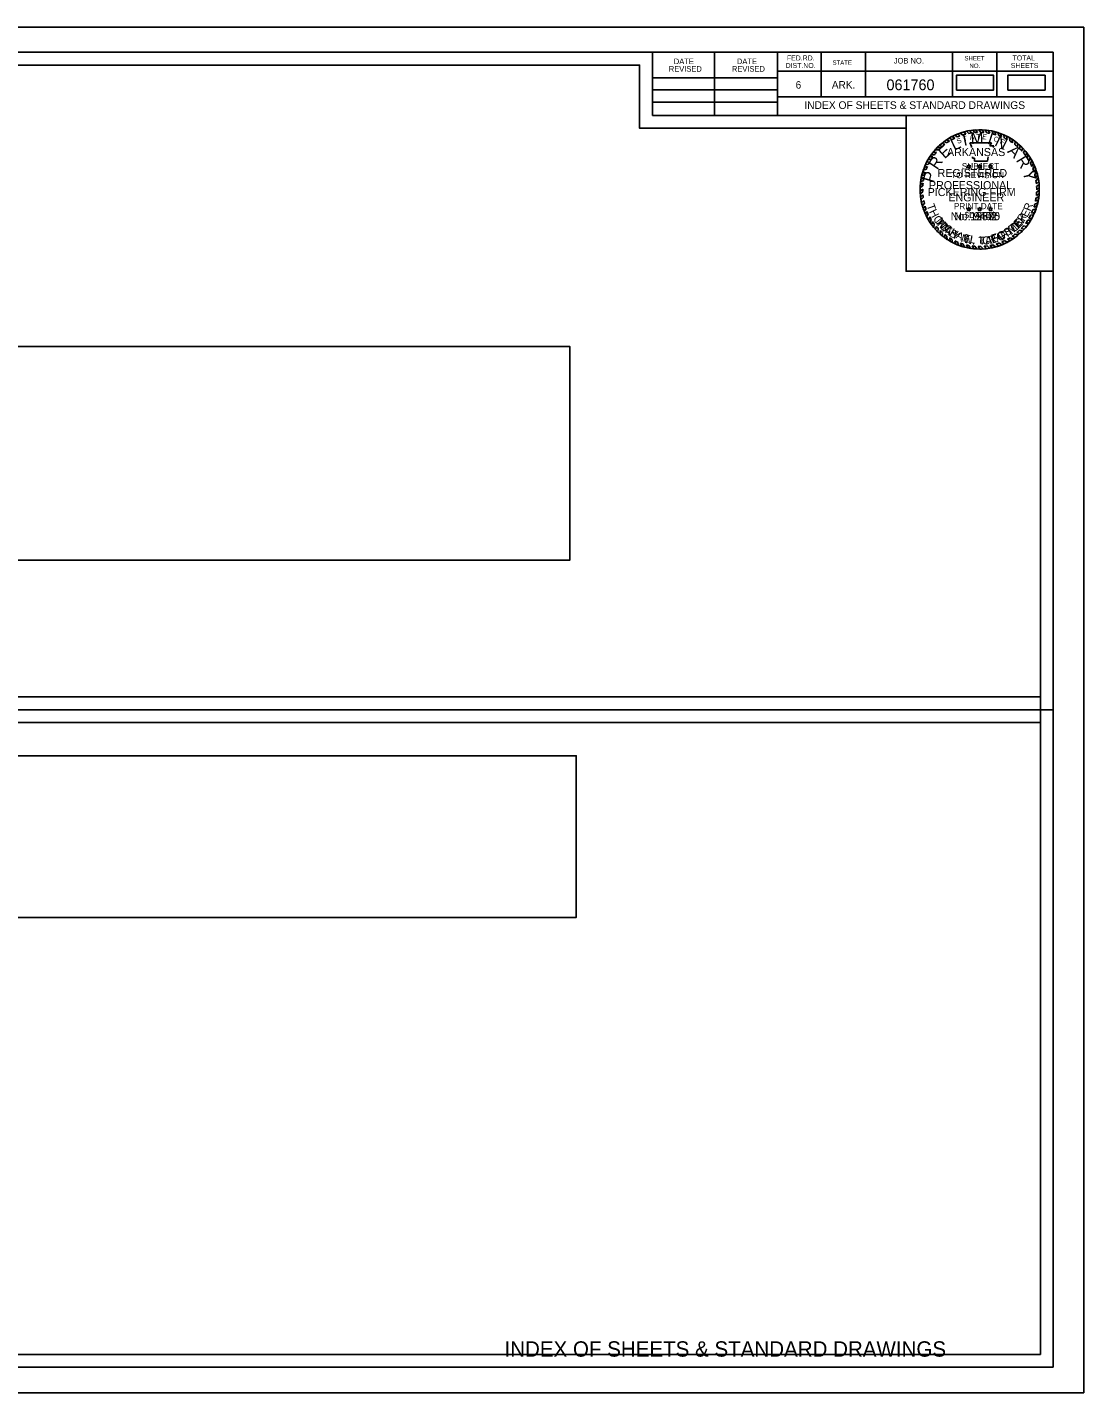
# Model space of a CAD drawing. Extents: x -12 to 321, y -380127 to -379914.
# Drawn here: x 155.9 to 320.9, y -380127 to -379913.7 of the extents above; entities that cross this region are included whole.
import ezdxf

# ---------------------------------------------------------------- set-up
doc = ezdxf.new("R2010")
doc.units = 0
for name, color, linetype in [('Default', 7, 'Continuous'), ('R_Border', 7, 'Continuous'), ('R_Border Notes', 7, 'Continuous'), ('R_Border Plan-Plan', 7, 'Continuous'), ('R_Border Title', 7, 'Continuous'), ('R_No Plot', 7, 'Continuous'), ('STAMP_PE_CRAFTON', 7, 'Continuous'), ('STAMP_PE_FOSTER', 7, 'Continuous'), ('STAMP_PE_SEAL-INFO', 7, 'Continuous'), ('STAMP_PE_TAEGTMEYER', 7, 'Continuous'), ('STAMP_PE_TXT', 7, 'Continuous'), ('STAMP_PRELIMINARY', 7, 'Continuous')]:
    doc.layers.add(name, color=color, linetype=linetype)

msp = doc.modelspace()

# ---------------------------------------------------------------- linework, layer by layer
at = {"layer": 'Default'}
for points in [[(301.03, -379923.52), (306.86, -379923.52), (306.86, -379921.21), (301.03, -379921.21)], [(309.07, -379923.52), (314.9, -379923.52), (314.9, -379921.21), (309.07, -379921.21)], [(84.69, -379996.99), (240.61, -379996.99), (240.61, -379963.58), (84.69, -379963.58)], [(83.66, -380052.8), (241.64, -380052.8), (241.64, -380027.52), (83.66, -380027.52)]]:
    msp.add_lwpolyline(points, close=True, dxfattribs=at)
at = {"layer": 'R_Border'}
for p, q in [((0, -379917.61), (316.18, -379917.61)), ((253.54, -379927.49), (253.54, -379917.61)), ((263.22, -379927.49), (263.22, -379917.61)), ((273.08, -379917.61), (273.08, -379927.49)), ((279.92, -379917.61), (279.92, -379924.55)), ((286.86, -379917.61), (286.86, -379924.55)), ((300.44, -379917.61), (300.44, -379924.55)), ((307.38, -379917.61), (307.38, -379924.55)), ((316.18, -380123.07), (316.18, -379917.61)), ((253.54, -379921.63), (273.08, -379921.63)), ((316.18, -379920.55), (273.08, -379920.55)), ((316.18, -379920.53), (316.18, -379920.53)), ((253.54, -379923.49), (273.08, -379923.49)), ((253.54, -379925.43), (273.08, -379925.43)), ((316.18, -379924.55), (273.08, -379924.55)), ((276.04, -379924.55), (316.18, -379924.55)), ((316.18, -379927.49), (253.54, -379927.49)), ((316.18, -380123.07), (0, -380123.07))]:
    msp.add_line(p, q, dxfattribs=at)
at = {"layer": 'R_Border Plan-Plan'}
msp.add_line((0, -380020.34), (316.18, -380020.34), dxfattribs=at)
at = {"layer": 'R_No Plot'}
for points in [[(-12.41, -379913.71), (320.93, -379913.71), (320.93, -380127.05), (-12.41, -380127.05)], [(314.18, -380018.34), (2, -380018.34), (2, -379919.61), (251.54, -379919.61), (251.54, -379929.49), (269.08, -379929.49), (293.18, -379929.49), (293.18, -379951.82), (314.18, -379951.82)], [(2, -379919.61), (251.54, -379919.61), (251.54, -379929.49), (269.08, -379929.49), (293.18, -379929.49), (293.18, -379951.82), (314.18, -379951.82), (314.18, -380121.07), (2, -380121.07)], [(293.18, -379927.49), (316.18, -379927.49), (316.18, -379951.82), (293.18, -379951.82)], [(2, -380022.34), (314.18, -380022.34), (314.18, -380121.07), (2, -380121.07)]]:
    msp.add_lwpolyline(points, close=True, dxfattribs=at)
at = {"layer": 'STAMP_PE_SEAL-INFO'}
for p, q in [((300.35, -379930.79), (300.82, -379931.01)), ((300.78, -379930.57), (301.17, -379930.85)), ((301.29, -379930.36), (301.59, -379930.68)), ((301.64, -379930.23), (302.02, -379930.54)), ((302.23, -379930.05), (302.52, -379930.4)), ((302.62, -379929.95), (302.97, -379930.29)), ((303.1, -379929.86), (303.4, -379930.22)), ((303.62, -379929.78), (303.9, -379930.16)), ((304.35, -379930.14), (304.04, -379929.74)), ((304.85, -379930.13), (304.57, -379929.72)), ((305.31, -379930.15), (305.05, -379929.73)), ((305.81, -379930.2), (305.52, -379929.76)), ((306.24, -379930.27), (305.98, -379929.81)), ((306.8, -379930.39), (306.63, -379929.93)), ((307.2, -379930.49), (307.04, -379930.03)), ((307.65, -379930.64), (307.51, -379930.16)), ((308.07, -379930.8), (307.93, -379930.31)), ((308.53, -379931.01), (308.43, -379930.51)), ((308.98, -379931.24), (308.89, -379930.73)), ((297.72, -379932.84), (298.24, -379932.88)), ((298.04, -379932.5), (298.59, -379932.54)), ((298.38, -379932.17), (298.84, -379932.31)), ((298.72, -379931.87), (299.25, -379931.97)), ((299.1, -379931.55), (299.55, -379931.75)), ((299.52, -379931.28), (299.96, -379931.48)), ((299.9, -379931.04), (300.34, -379931.26)), ((303.15, -379931.75), (306.5, -379931.75)), ((303.27, -379932.06), (303.15, -379931.75)), ((303.38, -379932.36), (303.27, -379932.06)), ((303.39, -379932.47), (303.38, -379932.36)), ((306.5, -379931.75), (306.27, -379932.24)), ((306.27, -379932.24), (306.9, -379932.24)), ((306.9, -379932.24), (306.76, -379932.47)), ((309.37, -379931.46), (309.33, -379930.96)), ((309.8, -379931.75), (309.77, -379931.23)), ((310.16, -379932.02), (310.2, -379931.53)), ((310.61, -379932.39), (310.63, -379931.87)), ((310.92, -379932.68), (310.99, -379932.18)), ((311.28, -379933.05), (311.35, -379932.53)), ((311.55, -379933.37), (311.69, -379932.9)), ((296.38, -379934.79), (296.88, -379934.73)), ((296.61, -379934.37), (297.1, -379934.35)), ((296.86, -379933.97), (297.38, -379933.93)), ((297.1, -379933.62), (297.6, -379933.63)), ((297.37, -379933.25), (297.92, -379933.23)), ((303.58, -379934.18), (303.55, -379933.96)), ((303.89, -379934.18), (303.58, -379934.18)), ((303.89, -379934.61), (303.89, -379934.18)), ((305.92, -379934.61), (303.89, -379934.61)), ((305.94, -379934.27), (305.92, -379934.61)), ((306.01, -379933.96), (305.94, -379934.27)), ((311.88, -379933.79), (312.01, -379933.29)), ((312.1, -379934.1), (312.28, -379933.64)), ((312.41, -379934.6), (312.59, -379934.11)), ((312.61, -379934.97), (312.83, -379934.52)), ((312.84, -379935.45), (313.06, -379934.97)), ((295.96, -379937.18), (295.5, -379937.42)), ((295.6, -379936.93), (296.07, -379936.74)), ((295.7, -379936.52), (296.18, -379936.35)), ((295.86, -379936.02), (296.35, -379935.88)), ((296.01, -379935.61), (296.52, -379935.47)), ((296.2, -379935.18), (296.7, -379935.08)), ((312.98, -379935.79), (313.24, -379935.35)), ((313.17, -379936.34), (313.44, -379935.86)), ((313.28, -379936.7), (313.57, -379936.25)), ((313.41, -379937.26), (313.73, -379936.81)), ((295.78, -379938.5), (295.36, -379938.75)), ((295.77, -379938.99), (295.36, -379939.32)), ((295.82, -379938.07), (295.38, -379938.35)), ((295.88, -379937.63), (295.43, -379937.86)), ((313.48, -379937.64), (313.84, -379937.29)), ((313.55, -379938.15), (313.92, -379937.81)), ((313.58, -379938.57), (313.97, -379938.28)), ((313.58, -379939.49), (314, -379939.21)), ((313.59, -379939.09), (314, -379938.76)), ((295.77, -379939.4), (295.38, -379939.72)), ((295.81, -379939.89), (295.44, -379940.25)), ((295.86, -379940.32), (295.5, -379940.69)), ((295.94, -379940.78), (295.6, -379941.15)), ((296.03, -379941.2), (295.72, -379941.61)), ((313.29, -379941.34), (313.77, -379941.14)), ((313.4, -379940.88), (313.86, -379940.69)), ((313.49, -379940.39), (313.93, -379940.17)), ((313.54, -379940), (313.98, -379939.74)), ((296.15, -379941.64), (295.86, -379942.06)), ((296.3, -379942.07), (296.01, -379942.48)), ((296.46, -379942.49), (296.2, -379942.92)), ((296.63, -379942.88), (296.41, -379943.34)), ((296.87, -379943.34), (296.68, -379943.83)), ((312.36, -379943.56), (312.87, -379943.51)), ((312.64, -379943.06), (313.12, -379942.99)), ((312.8, -379942.73), (313.29, -379942.63)), ((313.01, -379942.21), (313.49, -379942.08)), ((313.15, -379941.83), (313.64, -379941.63)), ((297.1, -379943.74), (296.92, -379944.21)), ((297.31, -379944.05), (297.2, -379944.6)), ((297.59, -379944.44), (297.49, -379944.97)), ((297.89, -379944.82), (297.8, -379945.34)), ((298.19, -379945.16), (298.13, -379945.68)), ((298.52, -379945.48), (298.49, -379946.01)), ((310.91, -379945.42), (311.35, -379945.56)), ((311.16, -379945.16), (311.64, -379945.25)), ((311.55, -379944.73), (312.01, -379944.81)), ((311.85, -379944.33), (312.36, -379944.33)), ((312.19, -379943.84), (312.67, -379943.85)), ((298.86, -379945.8), (298.86, -379946.32)), ((299.22, -379946.09), (299.24, -379946.61)), ((299.56, -379946.34), (299.6, -379946.86)), ((299.99, -379946.62), (300.05, -379947.13)), ((300.34, -379946.83), (300.43, -379947.34)), ((300.82, -379947.08), (300.97, -379947.6)), ((301.19, -379947.25), (301.36, -379947.76)), ((301.68, -379947.44), (301.89, -379947.94)), ((302.09, -379947.57), (302.32, -379948.06)), ((302.6, -379947.71), (302.81, -379948.18)), ((303, -379947.8), (303.24, -379948.25)), ((306.28, -379947.81), (306.67, -379948.15)), ((306.77, -379947.71), (307.15, -379948.03)), ((307.23, -379947.58), (307.65, -379947.88)), ((307.73, -379947.42), (308.17, -379947.69)), ((308.14, -379947.26), (308.57, -379947.52)), ((308.6, -379947.05), (309.09, -379947.26)), ((309.01, -379946.83), (309.43, -379947.07)), ((309.43, -379946.59), (309.88, -379946.78)), ((309.77, -379946.36), (310.21, -379946.55)), ((310.23, -379946.02), (310.7, -379946.16)), ((310.5, -379945.79), (310.97, -379945.92)), ((303.5, -379947.88), (303.74, -379948.32)), ((303.93, -379947.93), (304.21, -379948.35)), ((304.42, -379947.95), (304.72, -379948.37)), ((304.88, -379947.95), (305.22, -379948.35)), ((305.4, -379947.93), (305.72, -379948.31)), ((305.84, -379947.88), (306.21, -379948.24))]:
    msp.add_line(p, q, dxfattribs=at)
for radius, start, end in [(9.32, 117.6544, 120.8099), (9.32, 111.3124, 114.7026), (8.91, 110.3086, 113.1659), (9.32, 105.2339, 109.0352), (8.91, 104.0352, 107.3615), (9.32, 99.7525, 102.7765), (8.91, 98.258, 101.0329), (9.32, 93.9381, 96.5517), (8.91, 92.1102, 95.0367), (9.32, 87.7298, 90.6707), (8.91, 85.9628, 88.9097), (9.32, 81.9732, 84.8236), (8.91, 79.9264, 82.696), (9.32, 75.3125, 77.9426), (8.91, 73.5575, 76.2314), (9.32, 69.6061, 72.3058), (8.91, 67.6248, 70.504), (9.32, 63.1329, 66.2704), (9.32, 135.4021, 138.3031), (8.91, 133.1331, 136.2562), (9.32, 129.7326, 132.5376), (8.91, 127.5297, 130.9683), (9.32, 123.6199, 126.5906), (8.91, 121.9746, 125.11), (8.91, 115.6869, 119.1583), (8.91, 61.1558, 64.3784), (9.32, 56.9003, 60.0942), (8.91, 54.9238, 58.2702), (8.91, 48.3016, 52.0395), (9.32, 50.3492, 53.7159), (8.91, 42.2212, 45.5512), (9.32, 44.3405, 47.3929), (9.32, 38.1247, 41.2316), (9.32, 152.864, 155.5189), (9.32, 147.0072, 149.899), (8.91, 151.0315, 153.573), (9.32, 141.6056, 144.4486), (8.91, 145.0197, 148.2104), (8.91, 139.301, 142.5873), (8.91, 36.135, 39.5311), (8.91, 29.9032, 33.6645), (9.32, 31.9614, 35.4294), (8.91, 23.7732, 27.2211), (9.32, 25.9391, 29.0125), (9.32, 164.3068, 166.894), (9.32, 158.4077, 161.0701), (8.91, 167.9048, 170.9039), (8.91, 162.4331, 165.0013), (8.91, 156.3402, 159.2319), (8.91, 17.6802, 21.4251), (9.32, 19.9538, 23.3141), (8.91, 11.5444, 15.2364), (9.32, 13.8421, 17.4447), (9.32, 175.7409, 178.2066), (9.32, 181.7251, 184.1626), (9.32, 170.0003, 172.6878), (8.91, 179.6454, 182.2633), (8.91, 173.73, 176.4734), (8.91, 5.7599, 9.0606), (8.91, 359.7329, 3.0639), (9.32, 7.5852, 10.8621), (9.32, 1.7215, 4.7268), (9.32, 355.7156, 358.9569), (9.32, 187.4204, 190.1927), (9.32, 193.0369, 195.9973), (8.91, 185.4539, 188.234), (8.91, 191.2274, 193.9858), (8.91, 341.777, 345.0925), (8.91, 348.0778, 351.3435), (8.91, 353.8632, 357.1274), (9.32, 343.8925, 347.035), (9.32, 349.8305, 353.0885), (9.32, 198.8967, 201.6281), (8.91, 196.9675, 199.8353), (9.32, 204.5479, 207.4328), (8.91, 202.7761, 205.4791), (8.91, 208.7883, 211.7934), (8.91, 329.5549, 333.2076), (8.91, 335.6038, 339.1858), (9.32, 331.4037, 334.9332), (9.32, 337.3837, 340.9933), (9.32, 210.8636, 213.6571), (9.32, 216.6115, 219.491), (8.91, 214.1838, 217.2747), (9.32, 222.48, 225.3801), (8.91, 220.3909, 223.3056), (8.91, 226.2494, 229.2407), (8.91, 310.7744, 314.3161), (9.32, 312.4518, 315.6633), (8.91, 316.6531, 320.3711), (9.32, 318.2846, 321.8043), (8.91, 323.5851, 327.4407), (9.32, 325.4405, 328.9872), (9.32, 228.3665, 231.348), (8.91, 232.229, 234.9336), (9.32, 234.295, 236.9452), (8.91, 238.2223, 240.8353), (9.32, 240.1977, 242.8613), (8.91, 244.3204, 246.9486), (9.32, 246.576, 249.1558), (8.91, 250.3491, 253.1216), (8.91, 256.505, 259.1192), (8.91, 280.3459, 283.5814), (8.91, 286.6423, 289.9783), (9.32, 288.5709, 291.9733), (8.91, 292.8745, 296.1185), (9.32, 294.6481, 298.2166), (8.91, 299.0768, 302.1724), (9.32, 300.621, 303.8703), (8.91, 304.823, 308.5143), (9.32, 306.3721, 310.208), (9.32, 252.5967, 255.3252), (9.32, 258.4433, 261.1398), (8.91, 262.3783, 265.2012), (9.32, 264.1978, 267.1009), (8.91, 268.3215, 271.277), (9.32, 270.2548, 273.3361), (8.91, 274.6157, 277.4486), (9.32, 276.4239, 279.4357), (9.32, 282.3199, 285.3702)]:
    msp.add_arc((304.68, -379939.04), radius, start, end, dxfattribs=at)
at = {"layer": 'STAMP_PE_TXT'}
for p, q in [((302.86, -379935.47), (302.66, -379935.33)), ((302.66, -379935.33), (302.91, -379935.33)), ((302.78, -379935.71), (302.86, -379935.47)), ((302.98, -379935.56), (302.78, -379935.71)), ((302.91, -379935.33), (302.98, -379935.09)), ((302.98, -379935.09), (303.06, -379935.33)), ((303.18, -379935.71), (302.98, -379935.56)), ((303.06, -379935.33), (303.3, -379935.33)), ((303.3, -379935.33), (303.1, -379935.47)), ((303.1, -379935.47), (303.18, -379935.71)), ((304.56, -379935.47), (304.36, -379935.33)), ((304.36, -379935.33), (304.6, -379935.33)), ((304.48, -379935.71), (304.56, -379935.47)), ((304.68, -379935.56), (304.48, -379935.71)), ((304.6, -379935.33), (304.68, -379935.09)), ((304.68, -379935.09), (304.76, -379935.33)), ((304.88, -379935.71), (304.68, -379935.56)), ((304.76, -379935.33), (305, -379935.33)), ((305, -379935.33), (304.8, -379935.47)), ((304.8, -379935.47), (304.88, -379935.71)), ((306.26, -379935.47), (306.06, -379935.33)), ((306.06, -379935.33), (306.3, -379935.33)), ((306.18, -379935.71), (306.26, -379935.47)), ((306.38, -379935.56), (306.18, -379935.71)), ((306.3, -379935.33), (306.38, -379935.09)), ((306.38, -379935.09), (306.45, -379935.33)), ((306.58, -379935.71), (306.38, -379935.56)), ((306.45, -379935.33), (306.7, -379935.33)), ((306.7, -379935.33), (306.5, -379935.47)), ((306.5, -379935.47), (306.58, -379935.71)), ((302.86, -379942.18), (302.66, -379942.03)), ((302.66, -379942.03), (302.91, -379942.03)), ((302.78, -379942.41), (302.86, -379942.18)), ((302.98, -379942.27), (302.78, -379942.41)), ((302.91, -379942.03), (302.98, -379941.8)), ((302.98, -379941.8), (303.06, -379942.03)), ((303.18, -379942.41), (302.98, -379942.27)), ((303.06, -379942.03), (303.3, -379942.03)), ((303.3, -379942.03), (303.1, -379942.18)), ((303.1, -379942.18), (303.18, -379942.41)), ((304.56, -379942.18), (304.36, -379942.03)), ((304.36, -379942.03), (304.6, -379942.03)), ((304.48, -379942.41), (304.56, -379942.18)), ((304.68, -379942.27), (304.48, -379942.41)), ((304.6, -379942.03), (304.68, -379941.8)), ((304.68, -379941.8), (304.76, -379942.03)), ((304.88, -379942.41), (304.68, -379942.27)), ((304.76, -379942.03), (305, -379942.03)), ((305, -379942.03), (304.8, -379942.18)), ((304.8, -379942.18), (304.88, -379942.41)), ((306.26, -379942.18), (306.06, -379942.03)), ((306.06, -379942.03), (306.3, -379942.03)), ((306.18, -379942.41), (306.26, -379942.18)), ((306.38, -379942.27), (306.18, -379942.41)), ((306.3, -379942.03), (306.38, -379941.8)), ((306.38, -379941.8), (306.45, -379942.03)), ((306.58, -379942.41), (306.38, -379942.27)), ((306.45, -379942.03), (306.7, -379942.03)), ((306.7, -379942.03), (306.5, -379942.18)), ((306.5, -379942.18), (306.58, -379942.41))]:
    msp.add_line(p, q, dxfattribs=at)
at = {"layer": 'STAMP_PRELIMINARY'}
msp.add_circle((304.68, -379939.04), 9.32, dxfattribs=at)

# ---------------------------------------------------------------- texts
at = {"layer": 'R_Border'}
for s, height, p in [('REVISED', 0.879, (256.1, -379920.65)), ('DATE', 0.879, (256.88, -379919.47)), ('REVISED', 0.879, (265.96, -379920.65)), ('DATE', 0.879, (266.74, -379919.47)), ('DIST.NO.', 0.782, (274.36, -379920.07)), ('FED.RD.', 0.782, (274.56, -379918.89)), ('STATE', 0.684, (281.68, -379919.57)), ('JOB NO.', 0.879, (291.26, -379919.37)), ('SHEET', 0.684, (302.3, -379918.89)), ('NO.', 0.684, (303.08, -379920.07)), ('SHEETS', 0.782, (309.54, -379920.07)), ('TOTAL', 0.782, (309.82, -379918.89)), ('6', 1.17, (275.92, -379923.29)), ('ARK.', 1.172, (281.58, -379923.29))]:
    msp.add_text(s, height=height, dxfattribs=at).set_placement(p)
at = {"layer": 'R_Border Notes'}
for s, height, p in [('061760', 1.68, (290.12, -379923.54)), ('INDEX OF SHEETS & STANDARD DRAWINGS', 1.2, (277.27, -379926.47))]:
    msp.add_text(s, height=height, dxfattribs=at).set_placement(p)
at = {"layer": 'R_Border Title'}
msp.add_text('INDEX OF SHEETS & STANDARD DRAWINGS', height=2.4, dxfattribs=at).set_placement((230.42, -380121.42))
at = {"layer": 'STAMP_PE_CRAFTON'}
for s, rotation, p in [('T', 310.7442, (297.65, -379944.15)), ('N', 49.2411, (310.96, -379945.02)), ('O', 317.6422, (298.31, -379944.96)), ('N', 324.4537, (299.16, -379945.74)), ('Y', 331.1686, (300.19, -379946.46)), ('F', 28.7821, (308.34, -379946.91)), ('T', 34.1136, (309.26, -379946.4)), ('O', 41.8391, (310.12, -379945.8)), ('N', 347.4752, (302.25, -379947.37)), ('.', 356.8926, (303.48, -379947.65)), ('C', 6.0117, (305.15, -379947.7)), ('R', 14.8189, (306.25, -379947.59)), ('A', 20.5125, (307.36, -379947.29))]:
    msp.add_text(s, height=1.25, rotation=rotation, dxfattribs=at).set_placement(p)
msp.add_text('No. 12370', height=1.25, dxfattribs=at).set_placement((300.14, -379943.85))
at = {"layer": 'STAMP_PE_FOSTER'}
for s, rotation, p in [('M', 308.339, (297.8, -379944.02)), ('E', 46.9613, (310.68, -379945.05)), ('R', 54.5031, (311.4, -379944.23)), ('I', 314.1842, (298.59, -379944.96)), ('C', 319.8733, (298.95, -379945.31)), ('H', 327.7235, (299.88, -379946.05)), ('A', 335.7276, (300.86, -379946.63)), ('O', 23.719, (307.76, -379946.96)), ('S', 31.7234, (308.87, -379946.43)), ('T', 39.4194, (309.82, -379945.8)), ('E', 343.5779, (302, -379947.1)), ('L', 350.8115, (303.05, -379947.38)), ('L', 1.2666, (304.59, -379947.53)), ('.', 6.8035, (305.64, -379947.48)), ('F', 15.8691, (306.71, -379947.29))]:
    msp.add_text(s, height=1.2, rotation=rotation, dxfattribs=at).set_placement(p)
msp.add_text('No. 9402', height=1.25, dxfattribs=at).set_placement((300.67, -379943.85))
at = {"layer": 'STAMP_PE_TAEGTMEYER'}
for s, rotation, p in [('T', 289.646, (296.37, -379941.53)), ('R', 69.57, (312.63, -379942.53)), ('H', 296.7339, (296.73, -379942.52)), ('O', 303.7708, (297.33, -379943.63)), ('Y', 53.9986, (311.46, -379944.45)), ('E', 63.0984, (312.13, -379943.51)), ('M', 314.2033, (297.98, -379944.58)), ('A', 321.0594, (298.94, -379945.54)), ('S', 327.8239, (299.77, -379946.19)), ('G', 23.3052, (307.68, -379947.18)), ('T', 31.466, (308.78, -379946.69)), ('M', 39.3, (309.68, -379946.15)), ('E', 46.8094, (310.72, -379945.27)), ('N', 344.2727, (301.67, -379947.19)), ('.', 350.6464, (302.88, -379947.52)), ('T', 3.0061, (304.54, -379947.72)), ('A', 8.9826, (305.59, -379947.67)), ('E', 17.6836, (306.63, -379947.51))]:
    msp.add_text(s, height=1.25, rotation=rotation, dxfattribs=at).set_placement(p)
msp.add_text('No. 19605', height=1.25, dxfattribs=at).set_placement((300.14, -379943.85))
at = {"layer": 'STAMP_PE_TXT'}
for s, rotation, p in [('T', 16.311, (302.2, -379931.57)), ('A', 9.0679, (303.16, -379931.31)), ('T', 1.8248, (304.15, -379931.19)), ('E', 355.2002, (305.06, -379931.18)), ('O', 342.2506, (306.79, -379931.45)), ('S', 23.5541, (301.28, -379931.94)), ('F', 335.0075, (307.75, -379931.79))]:
    msp.add_text(s, height=0.781, rotation=rotation, dxfattribs=at).set_placement(p)
for s, p in [('ARKANSAS', (299.57, -379933.83)), ('REGISTERED', (298.1, -379937.1)), ('PROFESSIONAL', (296.75, -379939)), ('ENGINEER', (299.79, -379940.91))]:
    msp.add_text(s, height=1.25, dxfattribs=at).set_placement(p)
at = {"layer": 'STAMP_PRELIMINARY'}
for s, rotation, p in [('I', 12.5248, (302.22, -379932.26)), ('M', 3.1074, (303.32, -379931.95)), ('I', 342.3164, (305.78, -379931.88)), ('N', 333.9382, (306.89, -379932.15)), ('E', 42.3578, (299.21, -379934.35)), ('L', 25.513, (300.69, -379933.02)), ('A', 315.6579, (308.92, -379933.18)), ('R', 56.2292, (298.05, -379936.08)), ('R', 301.3831, (310.29, -379934.49)), ('P', 73.913, (297.5, -379938.1)), ('Y', 283.2593, (311.38, -379936.28))]:
    msp.add_text(s, height=1.8, rotation=rotation, dxfattribs=at).set_placement(p)
for s, height, p in [('SUBJECT', 0.96, (301.88, -379935.89)), ('TO REVISION', 0.96, (300.22, -379937.28)), ('PICKERING FIRM', 1.25, (296.55, -379940.08)), ('PRINT DATE', 0.96, (300.64, -379942.13)), ('$DATE$', 0.96, (302.31, -379943.51))]:
    msp.add_text(s, height=height, dxfattribs=at).set_placement(p)

doc.saveas('drawing.dxf')
